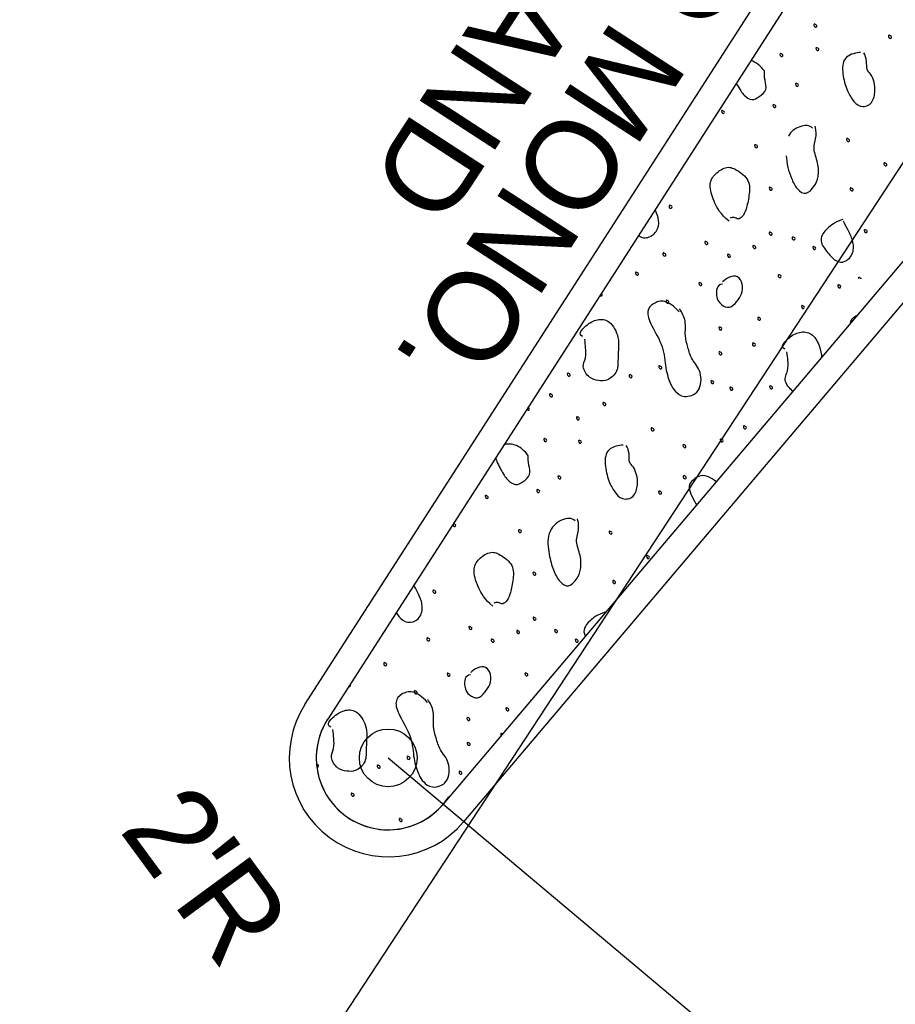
# Model space of a CAD drawing. Extents: x 1763480 to 1764420, y 711010 to 712012.
# Drawn here: x 1763854.99 to 1763879.33, y 711453.06 to 711480.44 of the extents above; entities that cross this region are included whole.
import ezdxf

# ---------------------------------------------------------------- set-up
doc = ezdxf.new("R2010")
doc.units = 0
for name, color, linetype in [('Old_Level_10', 7, 'Continuous'), ('Prop Conc Island Cover', 7, 'Continuous'), ('Prop Grid Mask', 7, 'Continuous'), ('Prop Lane Lines', 7, 'Continuous'), ('Sheet Block Revision CELL', 7, 'Continuous')]:
    doc.layers.add(name, color=color, linetype=linetype)

msp = doc.modelspace()

# ---------------------------------------------------------------- linework, layer by layer
at = {"layer": 'Old_Level_10'}
for points in [[(1763877.093, 711480.32), (1763877.067, 711480.32), (1763877.062, 711480.243), (1763877.142, 711480.213), (1763877.162, 711480.275), (1763877.127, 711480.299), (1763877.105, 711480.308), (1763877.092, 711480.311)], [(1763879.166, 711480.008), (1763879.14, 711480.009), (1763879.136, 711479.93), (1763879.215, 711479.902), (1763879.235, 711479.966), (1763879.2, 711479.987), (1763879.178, 711479.997), (1763879.165, 711480.001)], [(1763877.146, 711479.666), (1763877.12, 711479.666), (1763877.119, 711479.59), (1763877.196, 711479.561), (1763877.218, 711479.623), (1763877.182, 711479.646), (1763877.159, 711479.655), (1763877.145, 711479.658)], [(1763876.147, 711479.503), (1763876.121, 711479.503), (1763876.118, 711479.425), (1763876.197, 711479.398), (1763876.217, 711479.459), (1763876.182, 711479.482), (1763876.159, 711479.491), (1763876.146, 711479.494)], [(1763878.369, 711479.525), (1763878.257, 711479.516), (1763877.898, 711479.455), (1763877.838, 711479.001), (1763877.966, 711478.498), (1763878.134, 711478.213), (1763878.322, 711477.988), (1763878.688, 711478.051), (1763878.785, 711478.435), (1763878.751, 711478.703), (1763878.663, 711478.93), (1763878.518, 711479.033), (1763878.553, 711479.283), (1763878.492, 711479.453), (1763878.454, 711479.517)], [(1763875.694, 711479.016), (1763875.591, 711479.153), (1763875.454, 711479.248), (1763875.318, 711479.306)], [(1763874.91, 711478.671), (1763875.011, 711478.488), (1763875.119, 711478.322), (1763875.353, 711478.174), (1763875.536, 711478.28), (1763875.789, 711478.485), (1763875.696, 711478.749), (1763875.689, 711478.945), (1763875.694, 711479.016)], [(1763876.576, 711478.672), (1763876.551, 711478.671), (1763876.55, 711478.596), (1763876.626, 711478.568), (1763876.647, 711478.629), (1763876.612, 711478.652), (1763876.588, 711478.661), (1763876.576, 711478.665)], [(1763875.951, 711478.083), (1763875.925, 711478.083), (1763875.921, 711478.007), (1763876.001, 711477.978), (1763876.021, 711478.04), (1763875.986, 711478.064), (1763875.963, 711478.073), (1763875.95, 711478.076)], [(1763874.52, 711477.92), (1763874.494, 711477.919), (1763874.492, 711477.845), (1763874.568, 711477.814), (1763874.59, 711477.875), (1763874.555, 711477.899), (1763874.532, 711477.908), (1763874.519, 711477.911)], [(1763876.299, 711476.655), (1763876.307, 711476.585), (1763876.337, 711476.304), (1763876.434, 711476.045), (1763876.591, 711475.698), (1763876.856, 711475.546), (1763877.093, 711475.802), (1763877.203, 711476.048), (1763877.199, 711476.457), (1763877.023, 711476.852), (1763877.165, 711477.217), (1763877.116, 711477.43), (1763877.101, 711477.473)], [(1763877.031, 711477.418), (1763876.956, 711477.511), (1763876.672, 711477.498), (1763876.428, 711477.33), (1763876.36, 711477.196)], [(1763875.44, 711476.967), (1763875.415, 711476.967), (1763875.412, 711476.892), (1763875.491, 711476.863), (1763875.51, 711476.922), (1763875.475, 711476.948), (1763875.452, 711476.956), (1763875.44, 711476.96)], [(1763878.001, 711477.14), (1763877.975, 711477.141), (1763877.972, 711477.064), (1763878.051, 711477.034), (1763878.071, 711477.096), (1763878.036, 711477.119), (1763878.013, 711477.128), (1763878, 711477.132)], [(1763874.709, 711474.832), (1763874.466, 711475.04), (1763874.305, 711475.331), (1763874.137, 711475.807), (1763874.259, 711476.119), (1763874.633, 711476.377), (1763874.894, 711476.293), (1763875.308, 711475.986), (1763875.271, 711475.539), (1763875.189, 711475.137), (1763875.082, 711474.944), (1763874.955, 711474.871), (1763874.861, 711474.956), (1763874.768, 711474.934), (1763874.74, 711474.915)], [(1763879.038, 711476.461), (1763879.012, 711476.462), (1763879.009, 711476.384), (1763879.088, 711476.354), (1763879.108, 711476.418), (1763879.073, 711476.44), (1763879.05, 711476.449), (1763879.037, 711476.453)], [(1763875.847, 711475.786), (1763875.821, 711475.786), (1763875.818, 711475.708), (1763875.896, 711475.681), (1763875.918, 711475.742), (1763875.882, 711475.765), (1763875.86, 711475.775), (1763875.847, 711475.778)], [(1763878.1, 711475.767), (1763878.073, 711475.767), (1763878.07, 711475.69), (1763878.149, 711475.66), (1763878.169, 711475.724), (1763878.134, 711475.746), (1763878.111, 711475.755), (1763878.099, 711475.758)], [(1763873.065, 711475.281), (1763873.039, 711475.282), (1763873.036, 711475.204), (1763873.114, 711475.177), (1763873.136, 711475.237), (1763873.101, 711475.26), (1763873.078, 711475.269), (1763873.066, 711475.272)], [(1763872.194, 711474.443), (1763872.271, 711474.364), (1763872.51, 711474.351), (1763872.769, 711474.605), (1763872.757, 711474.947), (1763872.676, 711475.1), (1763872.649, 711475.152)], [(1763877.873, 711474.883), (1763877.651, 711474.803), (1763877.429, 711474.648), (1763877.192, 711474.319), (1763877.409, 711473.999), (1763877.683, 711473.694), (1763877.929, 711473.671), (1763878.193, 711473.929), (1763878.163, 711474.311), (1763878.018, 711474.583), (1763877.929, 711474.756), (1763877.889, 711474.839)], [(1763875.85, 711474.536), (1763875.823, 711474.537), (1763875.82, 711474.458), (1763875.898, 711474.431), (1763875.921, 711474.493), (1763875.884, 711474.515), (1763875.861, 711474.524), (1763875.849, 711474.528)], [(1763878.489, 711474.605), (1763878.463, 711474.605), (1763878.46, 711474.527), (1763878.538, 711474.5), (1763878.56, 711474.561), (1763878.525, 711474.584), (1763878.502, 711474.593), (1763878.49, 711474.596)], [(1763874.063, 711474.278), (1763874.037, 711474.279), (1763874.034, 711474.201), (1763874.113, 711474.171), (1763874.133, 711474.234), (1763874.098, 711474.256), (1763874.075, 711474.265), (1763874.062, 711474.268)], [(1763875.393, 711474.165), (1763875.366, 711474.166), (1763875.365, 711474.089), (1763875.443, 711474.06), (1763875.464, 711474.12), (1763875.428, 711474.144), (1763875.405, 711474.153), (1763875.392, 711474.156)], [(1763876.484, 711474.402), (1763876.458, 711474.402), (1763876.454, 711474.325), (1763876.534, 711474.296), (1763876.554, 711474.359), (1763876.519, 711474.382), (1763876.496, 711474.391), (1763876.483, 711474.394)], [(1763872.894, 711473.956), (1763872.867, 711473.956), (1763872.863, 711473.879), (1763872.943, 711473.849), (1763872.963, 711473.912), (1763872.928, 711473.935), (1763872.905, 711473.944), (1763872.893, 711473.947)], [(1763874.688, 711473.921), (1763874.662, 711473.922), (1763874.659, 711473.844), (1763874.738, 711473.815), (1763874.758, 711473.876), (1763874.723, 711473.9), (1763874.7, 711473.909), (1763874.687, 711473.912)], [(1763877.059, 711474.136), (1763877.033, 711474.136), (1763877.031, 711474.058), (1763877.109, 711474.031), (1763877.13, 711474.093), (1763877.094, 711474.115), (1763877.071, 711474.123), (1763877.058, 711474.127)], [(1763872.132, 711473.424), (1763872.106, 711473.425), (1763872.101, 711473.346), (1763872.181, 711473.318), (1763872.202, 711473.381), (1763872.166, 711473.403), (1763872.144, 711473.413), (1763872.131, 711473.417)], [(1763876.094, 711473.354), (1763876.068, 711473.354), (1763876.065, 711473.277), (1763876.145, 711473.247), (1763876.165, 711473.309), (1763876.13, 711473.333), (1763876.107, 711473.342), (1763876.093, 711473.345)], [(1763873.894, 711473.134), (1763873.868, 711473.134), (1763873.865, 711473.058), (1763873.944, 711473.029), (1763873.965, 711473.088), (1763873.93, 711473.114), (1763873.906, 711473.123), (1763873.893, 711473.126)], [(1763874.526, 711473.083), (1763874.361, 711473.074), (1763874.33, 711472.711), (1763874.481, 711472.505), (1763874.727, 711472.39), (1763874.931, 711472.594), (1763875.074, 711472.8), (1763875.11, 711473.097), (1763874.955, 711473.332), (1763874.722, 711473.296), (1763874.569, 711473.191), (1763874.532, 711473.144)], [(1763877.756, 711473.073), (1763877.73, 711473.073), (1763877.725, 711472.995), (1763877.805, 711472.966), (1763877.826, 711473.03), (1763877.79, 711473.051), (1763877.768, 711473.062), (1763877.755, 711473.065)], [(1763878.317, 711473.28), (1763878.302, 711473.277), (1763878.302, 711473.251), (1763878.305, 711473.237)], [(1763878.386, 711473.228), (1763878.386, 711473.232), (1763878.377, 711473.247), (1763878.352, 711473.259), (1763878.329, 711473.267), (1763878.316, 711473.271)], [(1763871.121, 711472.774), (1763871.122, 711472.772), (1763871.131, 711472.76), (1763871.17, 711472.741), (1763871.19, 711472.803), (1763871.167, 711472.822), (1763871.156, 711472.826), (1763871.155, 711472.827)], [(1763873.325, 711472.314), (1763873.176, 711472.479), (1763872.9, 711472.664), (1763872.595, 711472.552), (1763872.398, 711472.358), (1763872.522, 711471.958), (1763872.914, 711471.334), (1763872.927, 711470.742), (1763873.093, 711470.259), (1763873.204, 711470.113), (1763873.42, 711469.905), (1763873.928, 711470.04), (1763873.962, 711470.674), (1763873.653, 711470.984), (1763873.568, 711471.337), (1763873.47, 711471.63), (1763873.527, 711472.069), (1763873.405, 711472.293), (1763873.333, 711472.398)], [(1763872.98, 711472.644), (1763872.954, 711472.644), (1763872.951, 711472.569), (1763873.029, 711472.537), (1763873.05, 711472.601), (1763873.014, 711472.623), (1763872.992, 711472.632), (1763872.979, 711472.636)], [(1763876.745, 711472.495), (1763876.719, 711472.494), (1763876.715, 711472.419), (1763876.794, 711472.389), (1763876.815, 711472.451), (1763876.78, 711472.475), (1763876.757, 711472.484), (1763876.744, 711472.487)], [(1763870.64, 711471.627), (1763870.491, 711471.69), (1763870.746, 711471.963), (1763871.039, 711472.125), (1763871.391, 711472.1), (1763871.683, 711471.608), (1763871.605, 711471.042), (1763871.645, 711470.647), (1763871.308, 711470.369), (1763871.089, 711470.406), (1763870.821, 711470.442), (1763870.596, 711470.805), (1763870.747, 711471.014), (1763870.718, 711471.342), (1763870.711, 711471.449), (1763870.697, 711471.557)], [(1763875.528, 711472.171), (1763875.502, 711472.171), (1763875.499, 711472.096), (1763875.578, 711472.065), (1763875.598, 711472.127), (1763875.563, 711472.151), (1763875.54, 711472.16), (1763875.527, 711472.164)], [(1763878.271, 711472.207), (1763878.222, 711472.187), (1763878.105, 711472.123), (1763878.073, 711472.023), (1763878.071, 711471.971)], [(1763874.447, 711471.898), (1763874.421, 711471.898), (1763874.418, 711471.822), (1763874.497, 711471.793), (1763874.516, 711471.854), (1763874.482, 711471.878), (1763874.459, 711471.887), (1763874.446, 711471.891)], [(1763876.264, 711471.276), (1763876.115, 711471.338), (1763876.37, 711471.611), (1763876.663, 711471.774), (1763877.015, 711471.749), (1763877.243, 711471.377), (1763877.28, 711471.12), (1763877.284, 711471.042)], [(1763875.382, 711471.453), (1763875.355, 711471.453), (1763875.35, 711471.376), (1763875.431, 711471.346), (1763875.452, 711471.409), (1763875.416, 711471.432), (1763875.393, 711471.441), (1763875.381, 711471.444)], [(1763874.452, 711471.208), (1763874.426, 711471.209), (1763874.424, 711471.132), (1763874.502, 711471.103), (1763874.523, 711471.163), (1763874.488, 711471.187), (1763874.464, 711471.196), (1763874.451, 711471.199)], [(1763876.491, 711470.106), (1763876.443, 711470.129), (1763876.184, 711470.404), (1763876.371, 711470.662), (1763876.342, 711470.99), (1763876.335, 711471.098), (1763876.321, 711471.205)], [(1763870.235, 711470.613), (1763870.209, 711470.613), (1763870.206, 711470.535), (1763870.284, 711470.508), (1763870.306, 711470.569), (1763870.27, 711470.591), (1763870.247, 711470.602), (1763870.234, 711470.605)], [(1763872.781, 711470.82), (1763872.754, 711470.821), (1763872.75, 711470.743), (1763872.83, 711470.713), (1763872.85, 711470.776), (1763872.815, 711470.799), (1763872.793, 711470.809), (1763872.78, 711470.813)], [(1763871.954, 711470.571), (1763871.927, 711470.572), (1763871.926, 711470.495), (1763872.004, 711470.466), (1763872.024, 711470.526), (1763871.989, 711470.551), (1763871.967, 711470.56), (1763871.954, 711470.564)], [(1763874.225, 711470.407), (1763874.199, 711470.407), (1763874.197, 711470.332), (1763874.274, 711470.301), (1763874.295, 711470.362), (1763874.26, 711470.387), (1763874.237, 711470.396), (1763874.224, 711470.4)], [(1763874.754, 711470.226), (1763874.728, 711470.226), (1763874.723, 711470.149), (1763874.803, 711470.118), (1763874.824, 711470.182), (1763874.788, 711470.205), (1763874.766, 711470.213), (1763874.753, 711470.217)], [(1763875.859, 711470.261), (1763875.833, 711470.261), (1763875.83, 711470.183), (1763875.908, 711470.156), (1763875.93, 711470.217), (1763875.894, 711470.24), (1763875.871, 711470.25), (1763875.858, 711470.253)], [(1763869.744, 711470.037), (1763869.717, 711470.037), (1763869.715, 711469.96), (1763869.794, 711469.93), (1763869.814, 711469.993), (1763869.778, 711470.016), (1763869.756, 711470.024), (1763869.743, 711470.028)], [(1763871.227, 711469.795), (1763871.201, 711469.796), (1763871.198, 711469.717), (1763871.276, 711469.691), (1763871.298, 711469.751), (1763871.262, 711469.774), (1763871.239, 711469.783), (1763871.226, 711469.787)], [(1763869.09, 711469.613), (1763869.094, 711469.605), (1763869.1, 711469.587), (1763869.146, 711469.568), (1763869.164, 711469.627), (1763869.138, 711469.649), (1763869.123, 711469.655), (1763869.118, 711469.657)], [(1763870.49, 711469.403), (1763870.464, 711469.403), (1763870.459, 711469.326), (1763870.539, 711469.296), (1763870.56, 711469.358), (1763870.525, 711469.382), (1763870.502, 711469.391), (1763870.489, 711469.394)], [(1763872.563, 711469.091), (1763872.537, 711469.092), (1763872.533, 711469.013), (1763872.612, 711468.985), (1763872.633, 711469.049), (1763872.597, 711469.07), (1763872.575, 711469.08), (1763872.562, 711469.084)], [(1763875.131, 711469.148), (1763875.104, 711469.148), (1763875.102, 711469.071), (1763875.181, 711469.042), (1763875.201, 711469.104), (1763875.165, 711469.127), (1763875.142, 711469.136), (1763875.13, 711469.139)], [(1763869.582, 711468.798), (1763869.555, 711468.799), (1763869.552, 711468.72), (1763869.631, 711468.693), (1763869.652, 711468.755), (1763869.616, 711468.777), (1763869.593, 711468.786), (1763869.581, 711468.789)], [(1763870.543, 711468.749), (1763870.518, 711468.749), (1763870.517, 711468.673), (1763870.593, 711468.644), (1763870.615, 711468.706), (1763870.579, 711468.729), (1763870.556, 711468.738), (1763870.543, 711468.742)], [(1763874.482, 711468.783), (1763874.456, 711468.783), (1763874.455, 711468.708), (1763874.533, 711468.68), (1763874.551, 711468.738), (1763874.517, 711468.764), (1763874.494, 711468.772), (1763874.481, 711468.776)], [(1763869.128, 711468.311), (1763869.02, 711468.455), (1763868.819, 711468.635), (1763868.545, 711468.649), (1763868.444, 711468.607)], [(1763871.767, 711468.609), (1763871.655, 711468.6), (1763871.296, 711468.538), (1763871.236, 711468.084), (1763871.363, 711467.581), (1763871.531, 711467.296), (1763871.719, 711467.071), (1763872.085, 711467.135), (1763872.182, 711467.518), (1763872.148, 711467.786), (1763872.06, 711468.013), (1763871.915, 711468.116), (1763871.95, 711468.367), (1763871.889, 711468.537), (1763871.851, 711468.6)], [(1763873.449, 711468.627), (1763873.423, 711468.626), (1763873.421, 711468.551), (1763873.499, 711468.519), (1763873.519, 711468.582), (1763873.483, 711468.605), (1763873.461, 711468.614), (1763873.448, 711468.618)], [(1763868.221, 711468.26), (1763868.235, 711468.187), (1763868.377, 711467.896), (1763868.535, 711467.629), (1763868.788, 711467.469), (1763868.97, 711467.576), (1763869.223, 711467.781), (1763869.13, 711468.045), (1763869.123, 711468.24), (1763869.128, 711468.311)], [(1763869.974, 711467.755), (1763869.948, 711467.755), (1763869.947, 711467.679), (1763870.023, 711467.651), (1763870.045, 711467.712), (1763870.009, 711467.735), (1763869.986, 711467.744), (1763869.973, 711467.748)], [(1763873.46, 711467.763), (1763873.434, 711467.763), (1763873.43, 711467.685), (1763873.51, 711467.658), (1763873.53, 711467.719), (1763873.494, 711467.743), (1763873.472, 711467.752), (1763873.459, 711467.755)], [(1763874.356, 711467.585), (1763874.281, 711467.643), (1763874.107, 711467.772), (1763873.859, 711467.761), (1763873.647, 711467.595), (1763873.57, 711467.434), (1763873.675, 711467.179), (1763873.77, 711467.007), (1763873.811, 711466.941)], [(1763869.385, 711467.379), (1763869.36, 711467.378), (1763869.355, 711467.303), (1763869.435, 711467.273), (1763869.455, 711467.335), (1763869.42, 711467.359), (1763869.397, 711467.368), (1763869.384, 711467.371)], [(1763872.776, 711467.336), (1763872.749, 711467.337), (1763872.746, 711467.26), (1763872.825, 711467.23), (1763872.845, 711467.292), (1763872.81, 711467.315), (1763872.787, 711467.324), (1763872.775, 711467.328)], [(1763867.954, 711467.215), (1763867.928, 711467.215), (1763867.926, 711467.141), (1763868.003, 711467.11), (1763868.024, 711467.17), (1763867.989, 711467.194), (1763867.966, 711467.203), (1763867.953, 711467.207)], [(1763870.429, 711466.501), (1763870.354, 711466.594), (1763870.043, 711466.58), (1763869.629, 711466.188), (1763869.7, 711465.538), (1763869.816, 711465.127), (1763870, 711464.782), (1763870.254, 711464.629), (1763870.49, 711464.886), (1763870.601, 711465.132), (1763870.596, 711465.54), (1763870.42, 711465.935), (1763870.562, 711466.3), (1763870.513, 711466.514), (1763870.498, 711466.557)], [(1763867.034, 711466.413), (1763867.034, 711466.393), (1763867.035, 711466.352), (1763867.098, 711466.326), (1763867.119, 711466.389), (1763867.083, 711466.412), (1763867.06, 711466.421), (1763867.047, 711466.424)], [(1763867.048, 711466.433), (1763867.048, 711466.433), (1763867.048, 711466.433), (1763867.047, 711466.433)], [(1763868.875, 711466.263), (1763868.849, 711466.262), (1763868.846, 711466.187), (1763868.925, 711466.158), (1763868.944, 711466.218), (1763868.91, 711466.243), (1763868.887, 711466.252), (1763868.874, 711466.255)], [(1763871.399, 711466.224), (1763871.372, 711466.224), (1763871.369, 711466.147), (1763871.448, 711466.117), (1763871.468, 711466.179), (1763871.433, 711466.202), (1763871.41, 711466.211), (1763871.398, 711466.215)], [(1763868.143, 711464.127), (1763867.901, 711464.335), (1763867.739, 711464.626), (1763867.572, 711465.103), (1763867.693, 711465.415), (1763868.067, 711465.672), (1763868.328, 711465.589), (1763868.742, 711465.281), (1763868.705, 711464.834), (1763868.623, 711464.432), (1763868.516, 711464.239), (1763868.389, 711464.167), (1763868.295, 711464.252), (1763868.203, 711464.229), (1763868.174, 711464.211)], [(1763872.435, 711465.545), (1763872.409, 711465.545), (1763872.406, 711465.468), (1763872.485, 711465.438), (1763872.506, 711465.501), (1763872.47, 711465.524), (1763872.447, 711465.532), (1763872.434, 711465.536)], [(1763869.281, 711465.081), (1763869.255, 711465.081), (1763869.252, 711465.003), (1763869.33, 711464.976), (1763869.352, 711465.038), (1763869.317, 711465.061), (1763869.294, 711465.07), (1763869.282, 711465.073)], [(1763871.497, 711464.85), (1763871.471, 711464.851), (1763871.467, 711464.773), (1763871.546, 711464.743), (1763871.567, 711464.807), (1763871.531, 711464.829), (1763871.508, 711464.838), (1763871.496, 711464.842)], [(1763865.454, 711463.953), (1763865.504, 711463.882), (1763865.607, 711463.708), (1763865.94, 711463.642), (1763866.203, 711463.901), (1763866.173, 711464.283), (1763866.044, 711464.524), (1763865.971, 711464.666), (1763865.945, 711464.718)], [(1763866.5, 711464.577), (1763866.473, 711464.577), (1763866.471, 711464.499), (1763866.549, 711464.472), (1763866.57, 711464.532), (1763866.535, 711464.555), (1763866.512, 711464.564), (1763866.5, 711464.568)], [(1763869.284, 711463.832), (1763869.258, 711463.832), (1763869.255, 711463.753), (1763869.333, 711463.726), (1763869.355, 711463.788), (1763869.319, 711463.81), (1763869.296, 711463.819), (1763869.283, 711463.823)], [(1763871.27, 711463.966), (1763871.049, 711463.887), (1763870.827, 711463.731), (1763870.661, 711463.501), (1763870.671, 711463.398), (1763870.715, 711463.287)], [(1763867.497, 711463.574), (1763867.471, 711463.574), (1763867.468, 711463.497), (1763867.547, 711463.467), (1763867.567, 711463.529), (1763867.532, 711463.551), (1763867.509, 711463.56), (1763867.496, 711463.564)], [(1763869.881, 711463.485), (1763869.856, 711463.485), (1763869.851, 711463.409), (1763869.931, 711463.379), (1763869.952, 711463.443), (1763869.916, 711463.465), (1763869.893, 711463.474), (1763869.88, 711463.478)], [(1763866.328, 711463.251), (1763866.302, 711463.252), (1763866.297, 711463.174), (1763866.377, 711463.144), (1763866.397, 711463.207), (1763866.362, 711463.23), (1763866.339, 711463.239), (1763866.327, 711463.243)], [(1763868.123, 711463.216), (1763868.096, 711463.217), (1763868.093, 711463.14), (1763868.173, 711463.11), (1763868.192, 711463.172), (1763868.157, 711463.195), (1763868.134, 711463.204), (1763868.122, 711463.208)], [(1763868.827, 711463.46), (1763868.801, 711463.461), (1763868.799, 711463.384), (1763868.877, 711463.355), (1763868.898, 711463.415), (1763868.862, 711463.439), (1763868.839, 711463.448), (1763868.826, 711463.452)], [(1763870.456, 711463.219), (1763870.43, 711463.219), (1763870.429, 711463.141), (1763870.506, 711463.114), (1763870.527, 711463.176), (1763870.491, 711463.198), (1763870.468, 711463.207), (1763870.455, 711463.21)], [(1763865.131, 711462.563), (1763865.105, 711462.564), (1763865.1, 711462.485), (1763865.18, 711462.457), (1763865.201, 711462.52), (1763865.165, 711462.542), (1763865.143, 711462.552), (1763865.13, 711462.556)], [(1763867.525, 711462.222), (1763867.36, 711462.213), (1763867.329, 711461.85), (1763867.48, 711461.644), (1763867.726, 711461.529), (1763867.93, 711461.733), (1763868.073, 711461.94), (1763868.109, 711462.236), (1763867.954, 711462.472), (1763867.721, 711462.435), (1763867.568, 711462.331), (1763867.531, 711462.283)], [(1763866.893, 711462.273), (1763866.867, 711462.273), (1763866.864, 711462.197), (1763866.943, 711462.168), (1763866.964, 711462.228), (1763866.929, 711462.253), (1763866.905, 711462.262), (1763866.892, 711462.266)], [(1763869.056, 711462.281), (1763869.03, 711462.281), (1763869.027, 711462.204), (1763869.107, 711462.174), (1763869.127, 711462.236), (1763869.092, 711462.26), (1763869.068, 711462.269), (1763869.055, 711462.272)], [(1763864.135, 711461.9), (1763864.147, 711461.895), (1763864.173, 711461.888), (1763864.193, 711461.938), (1763864.176, 711461.953), (1763864.171, 711461.957)], [(1763866.324, 711461.453), (1763866.175, 711461.619), (1763865.899, 711461.804), (1763865.594, 711461.691), (1763865.397, 711461.497), (1763865.521, 711461.097), (1763865.913, 711460.473), (1763865.926, 711459.881), (1763866.092, 711459.398), (1763866.203, 711459.253), (1763866.419, 711459.044), (1763866.927, 711459.18), (1763866.961, 711459.814), (1763866.652, 711460.123), (1763866.567, 711460.476), (1763866.469, 711460.769), (1763866.526, 711461.208), (1763866.404, 711461.432), (1763866.332, 711461.538)], [(1763865.979, 711461.784), (1763865.953, 711461.783), (1763865.95, 711461.708), (1763866.028, 711461.676), (1763866.049, 711461.74), (1763866.013, 711461.763), (1763865.991, 711461.771), (1763865.978, 711461.775)], [(1763868.527, 711461.31), (1763868.501, 711461.31), (1763868.498, 711461.235), (1763868.577, 711461.204), (1763868.597, 711461.266), (1763868.562, 711461.291), (1763868.539, 711461.3), (1763868.526, 711461.303)], [(1763863.639, 711460.767), (1763863.49, 711460.829), (1763863.745, 711461.102), (1763864.038, 711461.264), (1763864.39, 711461.24), (1763864.682, 711460.747), (1763864.604, 711460.181), (1763864.644, 711459.786), (1763864.307, 711459.509), (1763864.088, 711459.545), (1763863.82, 711459.581), (1763863.595, 711459.944), (1763863.746, 711460.153), (1763863.717, 711460.481), (1763863.71, 711460.589), (1763863.696, 711460.696)], [(1763867.446, 711461.037), (1763867.42, 711461.037), (1763867.417, 711460.961), (1763867.496, 711460.932), (1763867.515, 711460.994), (1763867.481, 711461.017), (1763867.458, 711461.026), (1763867.445, 711461.03)], [(1763868.381, 711460.592), (1763868.359, 711460.593), (1763868.365, 711460.55), (1763868.377, 711460.526)], [(1763868.415, 711460.571), (1763868.403, 711460.576), (1763868.392, 711460.58), (1763868.38, 711460.584)], [(1763867.451, 711460.347), (1763867.425, 711460.348), (1763867.423, 711460.271), (1763867.501, 711460.242), (1763867.522, 711460.302), (1763867.487, 711460.326), (1763867.463, 711460.335), (1763867.45, 711460.339)], [(1763865.78, 711459.959), (1763865.753, 711459.96), (1763865.749, 711459.883), (1763865.829, 711459.853), (1763865.849, 711459.915), (1763865.814, 711459.938), (1763865.792, 711459.948), (1763865.779, 711459.952)], [(1763863.249, 711459.666), (1763863.26, 711459.661), (1763863.291, 711459.651), (1763863.304, 711459.707), (1763863.272, 711459.729), (1763863.252, 711459.738), (1763863.243, 711459.741)], [(1763864.953, 711459.71), (1763864.926, 711459.711), (1763864.925, 711459.634), (1763865.003, 711459.606), (1763865.023, 711459.666), (1763864.988, 711459.69), (1763864.966, 711459.699), (1763864.953, 711459.703)], [(1763867.224, 711459.546), (1763867.198, 711459.546), (1763867.196, 711459.472), (1763867.273, 711459.44), (1763867.294, 711459.502), (1763867.259, 711459.527), (1763867.236, 711459.536), (1763867.223, 711459.539)], [(1763864.226, 711458.934), (1763864.2, 711458.935), (1763864.197, 711458.857), (1763864.275, 711458.83), (1763864.297, 711458.89), (1763864.261, 711458.913), (1763864.238, 711458.922), (1763864.225, 711458.926)], [(1763865.562, 711458.23), (1763865.536, 711458.231), (1763865.532, 711458.152), (1763865.611, 711458.125), (1763865.632, 711458.188), (1763865.596, 711458.209), (1763865.574, 711458.219), (1763865.561, 711458.223)]]:
    msp.add_open_spline(points, degree=3, dxfattribs=at)
at = {"layer": 'Prop Conc Island Cover'}
for p, q in [((1763888.402, 711499.672), (1763863.551, 711460.991)), ((1763866.76, 711458.617), (1763896.699, 711493.963))]:
    msp.add_line(p, q, dxfattribs=at)
for end in [319.9767, 327.2804]:
    msp.add_arc((1763865.233, 711459.91), 2, 147.2804, end, dxfattribs=at)
at = {"layer": 'Prop Grid Mask'}
msp.add_line((1763865.233, 711459.91), (1763894.249, 711435.542), dxfattribs=at)
msp.add_circle((1763865.233, 711459.91), 0.802, dxfattribs=at)
at = {"layer": 'Prop Lane Lines'}
for p, q in [((1763862.92, 711461.396), (1763888.866, 711501.781)), ((1763867.332, 711458.132), (1763898.792, 711495.274))]:
    msp.add_line(p, q, dxfattribs=at)
msp.add_arc((1763865.233, 711459.91), 2.75, 147.2804, 319.7341, dxfattribs=at)
at = {"layer": 'Sheet Block Revision CELL'}
msp.add_line((1763852.839, 711435.72), (1763908.534, 711520.667), dxfattribs=at)

# ---------------------------------------------------------------- texts
at = {"layer": 'Prop Grid Mask'}
for s, rotation, p in [('PROPOSED MONO.', 236.9842, (1763882.337, 711497.181)), ('CONC. ISLAND', 236.9842, (1763877.603, 711495.87)), ("2'R", 306.325, (1763857.727, 711457.905))]:
    msp.add_text(s, height=2.5, rotation=rotation, dxfattribs=at).set_placement(p)

doc.saveas('drawing.dxf')
